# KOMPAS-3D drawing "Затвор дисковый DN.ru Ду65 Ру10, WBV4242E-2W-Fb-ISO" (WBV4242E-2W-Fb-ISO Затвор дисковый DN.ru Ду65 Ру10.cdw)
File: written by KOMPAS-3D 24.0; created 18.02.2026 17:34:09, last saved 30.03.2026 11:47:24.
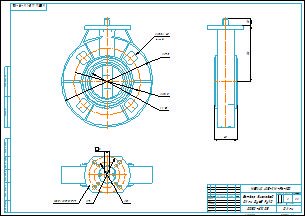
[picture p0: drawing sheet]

Document properties: Автор: R2D2; Форматы листов документа: A2; Полное имя файла: WBV4242E-2W-Fb-ISO Затвор дисковый DN.ru Ду65 Ру10.m3d; Масса: 1; Наименование: Затвор дисковый DN.ru Ду65 Ру10; Количество листов документа: 1; Примечание: D050-81205

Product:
- Part/product: Затвор дисковый DN.ru Ду65 Ру10  | designation WBV4242E-2W-Fb-ISO
    Масса: 1
    Раздел спецификации: Прочие изделия
    Форматы листов документа: A2
    Примечание: D050-81205

Views: Вид 1, Спереди, Проекционный вид 2, Проекционный вид 3
Referenced files in E:\Работа\Зайцев\WBV4242E-2W-Fb-ISO Затвор дисковый DN.ru Ду50-200 Ру10\DN65\: WBV4242E-2W-Fb-ISO Затвор дисковый DN.ru Ду65 Ру10.m3d
Referenced files in E:\Работа\Зайцев\Для компаса\: чертеж DN.ru А3.cdt
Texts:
  WBV4242E-2W-Fb-ISO
  ISO 5211 F05/F07
  чертеж DN.ru А3.cdt
  Затвор дисковый
  DN.ru Ду65 Ру10
  Затвор дисковый DN.ru Ду65 Ру10
  WBV4242E-2W-Fb-ISO Затвор дисковый DN.ru Ду65 Ру10
Dimensions and other numbers on the sheet: 0; 3; 2; 4; 179; 130,5; 4 отв.; 65; 45; 13; 110; 70; 50; 11; 1:1; 1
